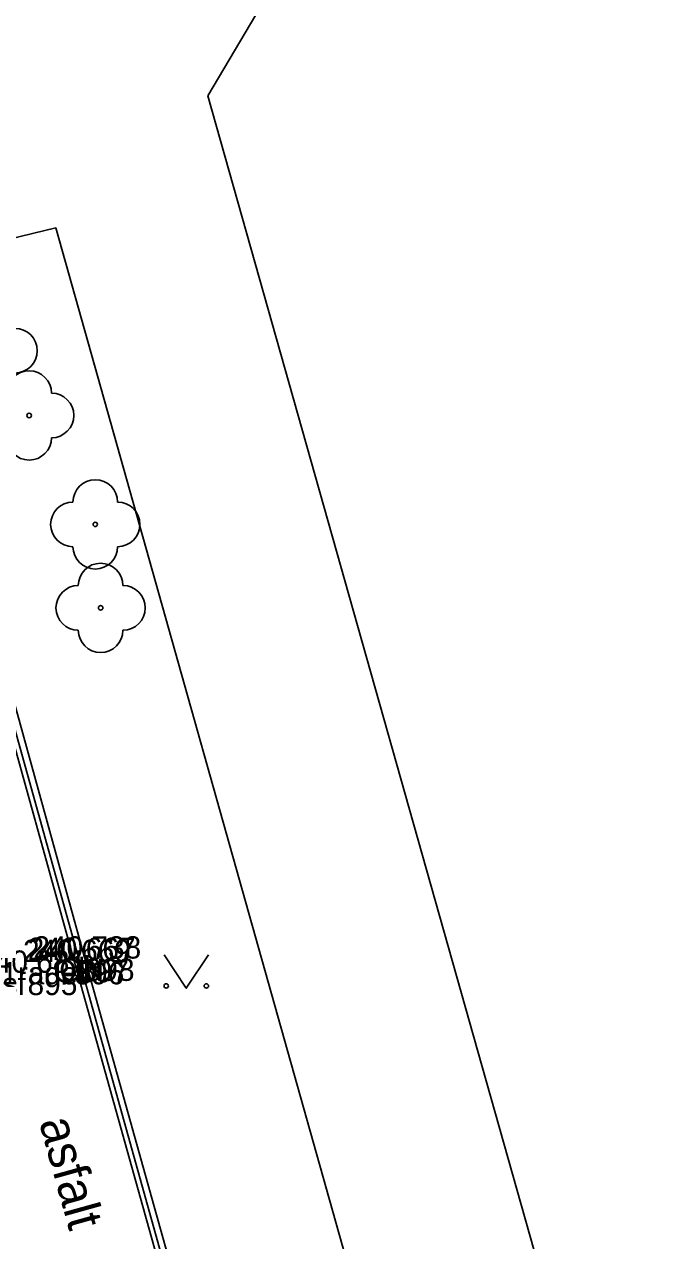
# Model space of a CAD drawing. Extents: x -599098 to -598820, y -1159597 to -1158744.
# Drawn here: x -598946.5 to -598932.11, y -1159153.04 to -1159125.79 of the extents above; entities that cross this region are included whole.
import ezdxf

# ---------------------------------------------------------------- set-up
doc = ezdxf.new("R2010")
doc.units = 0
for name, color, linetype in [('body', 7, 'Continuous'), ('druh pozemku stromy', 7, 'Continuous'), ('kresba', 7, 'Continuous'), ('kódy bodů', 7, 'Continuous'), ('popisy', 7, 'Continuous'), ('výšky bodů', 7, 'Continuous'), ('čísla bodů', 7, 'Continuous')]:
    doc.layers.add(name, color=color, linetype=linetype)

msp = doc.modelspace()

# ---------------------------------------------------------------- linework, layer by layer
at = {"layer": 'body'}
for p, q in [((-598945.376, -1159146.794), (-598945.376, -1159146.794)), ((-598945.272, -1159146.749), (-598945.272, -1159146.749)), ((-598945.146, -1159146.717), (-598945.146, -1159146.717)), ((-598946.426, -1159147.035), (-598946.426, -1159147.035))]:
    msp.add_line(p, q, dxfattribs=at)
at = {"layer": 'druh pozemku stromy'}
msp.add_lwpolyline([(-598943.37, -1159146.63), (-598942.87, -1159147.38), (-598942.37, -1159146.63)], dxfattribs=at)
for centre in [(-598946.39, -1159134.55), (-598944.91, -1159136.99), (-598944.79, -1159138.86), (-598943.32, -1159147.33), (-598942.421, -1159147.33)]:
    msp.add_circle(centre, 0.05, dxfattribs=at)
for centre, start, end in [((-598946.71, -1159133.1), 270, 90), ((-598946.39, -1159134.05), 0, 180), ((-598945.89, -1159134.55), 270, 90), ((-598946.39, -1159135.05), 180, 0), ((-598944.91, -1159136.49), 0, 180), ((-598945.41, -1159136.99), 90, 270), ((-598944.41, -1159136.99), 270, 90), ((-598944.91, -1159137.49), 180, 0), ((-598944.79, -1159138.36), 0, 180), ((-598945.29, -1159138.86), 90, 270), ((-598944.29, -1159138.86), 270, 90), ((-598944.79, -1159139.36), 180, 0)]:
    msp.add_arc(centre, 0.5, start, end, dxfattribs=at)
at = {"layer": 'kresba'}
for p, q in [((-598934.45, -1159113.98), (-598942.39, -1159127.39)), ((-598947.965, -1159130.878), (-598945.794, -1159130.345)), ((-598945.794, -1159130.345), (-598936.061, -1159164.919)), ((-598945.376, -1159146.794), (-598948.51, -1159135.517)), ((-598945.272, -1159146.749), (-598948.421, -1159135.492)), ((-598948.253, -1159135.448), (-598945.146, -1159146.717)), ((-598945.376, -1159146.794), (-598942.345, -1159157.638)), ((-598945.272, -1159146.749), (-598942.236, -1159157.623)), ((-598942.106, -1159157.587), (-598945.146, -1159146.717))]:
    msp.add_line(p, q, dxfattribs=at)
msp.add_lwpolyline([(-598942.39, -1159127.39), (-598932.11, -1159163.78)], dxfattribs=at)

# ---------------------------------------------------------------- texts
at = {"layer": 'kódy bodů'}
for s, p in [('1rade', (-598947.016, -1159147.294)), ('OD', (-598945.844, -1159147.249)), ('ON', (-598945.716, -1159147.217)), ('asf', (-598947.359, -1159147.535))]:
    msp.add_text(s, height=0.5, dxfattribs=at).set_placement(p)
at = {"layer": 'popisy'}
msp.add_text('asfalt', height=0.8, rotation=285.5601, dxfattribs=at).set_placement((-598946.172, -1159150.377))
at = {"layer": 'výšky bodů'}
for s, p in [('240.667', (-598946.424, -1159146.749)), ('240.738', (-598946.298, -1159146.717)), ('240.681', (-598947.534, -1159147.035)), ('240.669', (-598946.528, -1159146.794))]:
    msp.add_text(s, height=0.5, dxfattribs=at).set_placement(p)
at = {"layer": 'čísla bodů'}
for s, p in [('896', (-598945.376, -1159147.294)), ('897', (-598945.272, -1159147.249)), ('898', (-598945.146, -1159147.217)), ('895', (-598946.426, -1159147.535))]:
    msp.add_text(s, height=0.5, dxfattribs=at).set_placement(p)

doc.saveas('drawing.dxf')
